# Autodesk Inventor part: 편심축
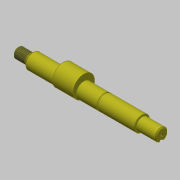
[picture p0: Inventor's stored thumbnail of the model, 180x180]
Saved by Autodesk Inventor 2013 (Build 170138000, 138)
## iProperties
Created: 2016-08
Part Number: 편심축
Material: 강철, 탄소
Document SubType Name: Modeling
Designer: mduedu
Density: 7.87 g/cm^3
Author: mduedu
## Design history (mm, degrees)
sketch "스케치1"
  geometry: L1 (-70, 0)-(70, 0); L2 (-70, 0)-(-70, 5); L3 (-70, 5)-(-56, 5); L4 (-56, 5)-(-56, 7.5); L5 (-56, 7.5)-(51, 7.5); L6 (51, 7.5)-(51, 6); L7 (51, 6)-(70, 6); L8 (70, 6)-(70, 0); 2 further points
  constraints: 16 end point, 5 parallel, 2 perpendicular, 1 coincident, 1 horizontal, 1 midpoint
  dimensions: "d0" = 140 distance of L1.start L1.end; "d2" = 14 distance of L2.end L3.end; "d3" = 19 distance of L6.end L7.end; "d4" = 10 diameter of L3 L1; "d5" = 15 diameter of L5 L1; "d6" = 12 diameter of L7 L1
revolve "회전1" sketch "스케치1" stored, may be unused: angle "d7" = 90 deg
sketch "스케치2"
  geometry: L1 (-56, -5)-(-56, 5) reference; L2 (70, -6)-(70, 6) reference; L3 (-56, 0)-(70, 0); L4 (-58, 4.5)-(-58, 5); L5 (-58, 5)-(-56, 5); L6 (-56, 5)-(-56, 4.5); L7 (-58, 4.5)-(-56, 4.5); 1 further point
  constraints: 10 end point, 2 midpoint, 1 parallel, 1 perpendicular, 1 point on line
  dimensions: "d8" = 2 distance of L4.end L5.end; "d10" = 10 diameter of L5 L3; "d11" = 9 diameter of L7 L3
revolve "회전2" sketch "스케치2" stored, may be unused: angle "d12" = 90 deg
node "작업 평면1"
sketch "스케치3"
  geometry: C1 r 10.5 at (0, 3); C2 r 7.5 at (0, 0) reference; 1 further point
  constraints: 1 centre point, 1 tangent, 1 vertical alignment
  dimensions: "d14" = 3 distance of C1.centre point (0, 0); "d15" = 21 diameter of C1 (derived)
extrude "돌출1" join sketch "스케치3" distance "d16" = 20; taper "d17" = 0 deg
sketch "스케치5"
  geometry: L1 (-70, -5)-(-70, 5) reference; L2 (70, -6)-(70, 6) reference; L3 (-70, 0)-(70, 0); L4 (-6, 7.5)-(51, 7.5) reference; L5 (15.15, 7.5)-(14, 7.5); L6 (14, 7.5)-(14, 7.15); L7 (14, 7.15)-(15.15, 7.15); L8 (15.15, 7.15)-(15.15, 7.5); 1 further point
  constraints: 10 end point, 2 midpoint, 2 parallel, 1 horizontal, 1 perpendicular, 1 point on line
  dimensions: "d19" = 56 distance between parallel lines of L6 L2; "d20" = 1.15 distance between parallel lines of L8 L6; "d21" = 14.3 diameter of L7 L3
revolve "회전3" sketch "스케치5" stored, may be unused: angle "d22" = 90 deg
node "작업 평면3"
sketch "스케치6"
  geometry: L1 (9.5, 7.5)-(9.5, -7.5) reference; L2 (7.5, 2)-(-9.5, 2); L3 (-9.5, 2)-(-9.5, -2); L4 (-9.5, -2)-(7.5, -2); L5 (-9.5, 6)-(-9.5, -6) reference; A1 r 2 centre (7.5, 0) between (7.5, -2) and (7.5, 2); 2 further points
  constraints: 6 end point, 3 tangent, 2 midpoint, 2 point on circle, 1 centre point, 1 horizontal, 1 horizontal alignment, 1 parallel, 1 perpendicular
  dimensions: "d23" = 4 distance between parallel lines of L4 L2
extrude "돌출2" cut sketch "스케치6" distance "d25" = 2.5; taper "d26" = 0 deg
feature "스레드1" dims "d27" = 10, "d28" = 0
chamfer "모따기5" distance "d41" = 0.5; stored, may be unused: second distance "d42" = 2, angle "d43" = 45 deg
chamfer "모따기6" distance "d44" = 0.5; stored, may be unused: second distance "d45" = 2, angle "d46" = 45 deg
chamfer "모따기7" distance "d47" = 1; stored, may be unused: second distance "d48" = 2, angle "d49" = 45 deg
chamfer "모따기8" distance "d50" = 1; stored, may be unused: second distance "d51" = 2, angle "d52" = 45 deg
sketch "스케치8"
  geometry: 1 further point
hole "구멍1" sketch "스케치8" at (2, 3.5) diameter "d53" = 3.242; stored, may be unused: countersink angle "d57" = 90 deg, drill point angle "d59" = 120 deg; dims "d54" = 10, "d55" = 4, "d56" = 2, "d58" = 12
node "솔리드1"
other parameters: "d13" = -44
